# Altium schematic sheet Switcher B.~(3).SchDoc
size 431 x 279 mm; Organization: UTVATE; Address1: ADDRESS 1; Address2: ADDRESS 2; Address3: ADDRESS 3; Address4: ADDRESS 4; Revision: -; SheetNumber: 1; SheetTotal: 1; ENG_APP_DATE: YYYY/MM/DD; DSN_APP_DATE: YYYY/MM/DD; CHK_APP_DATE: YYYY/MM/DD
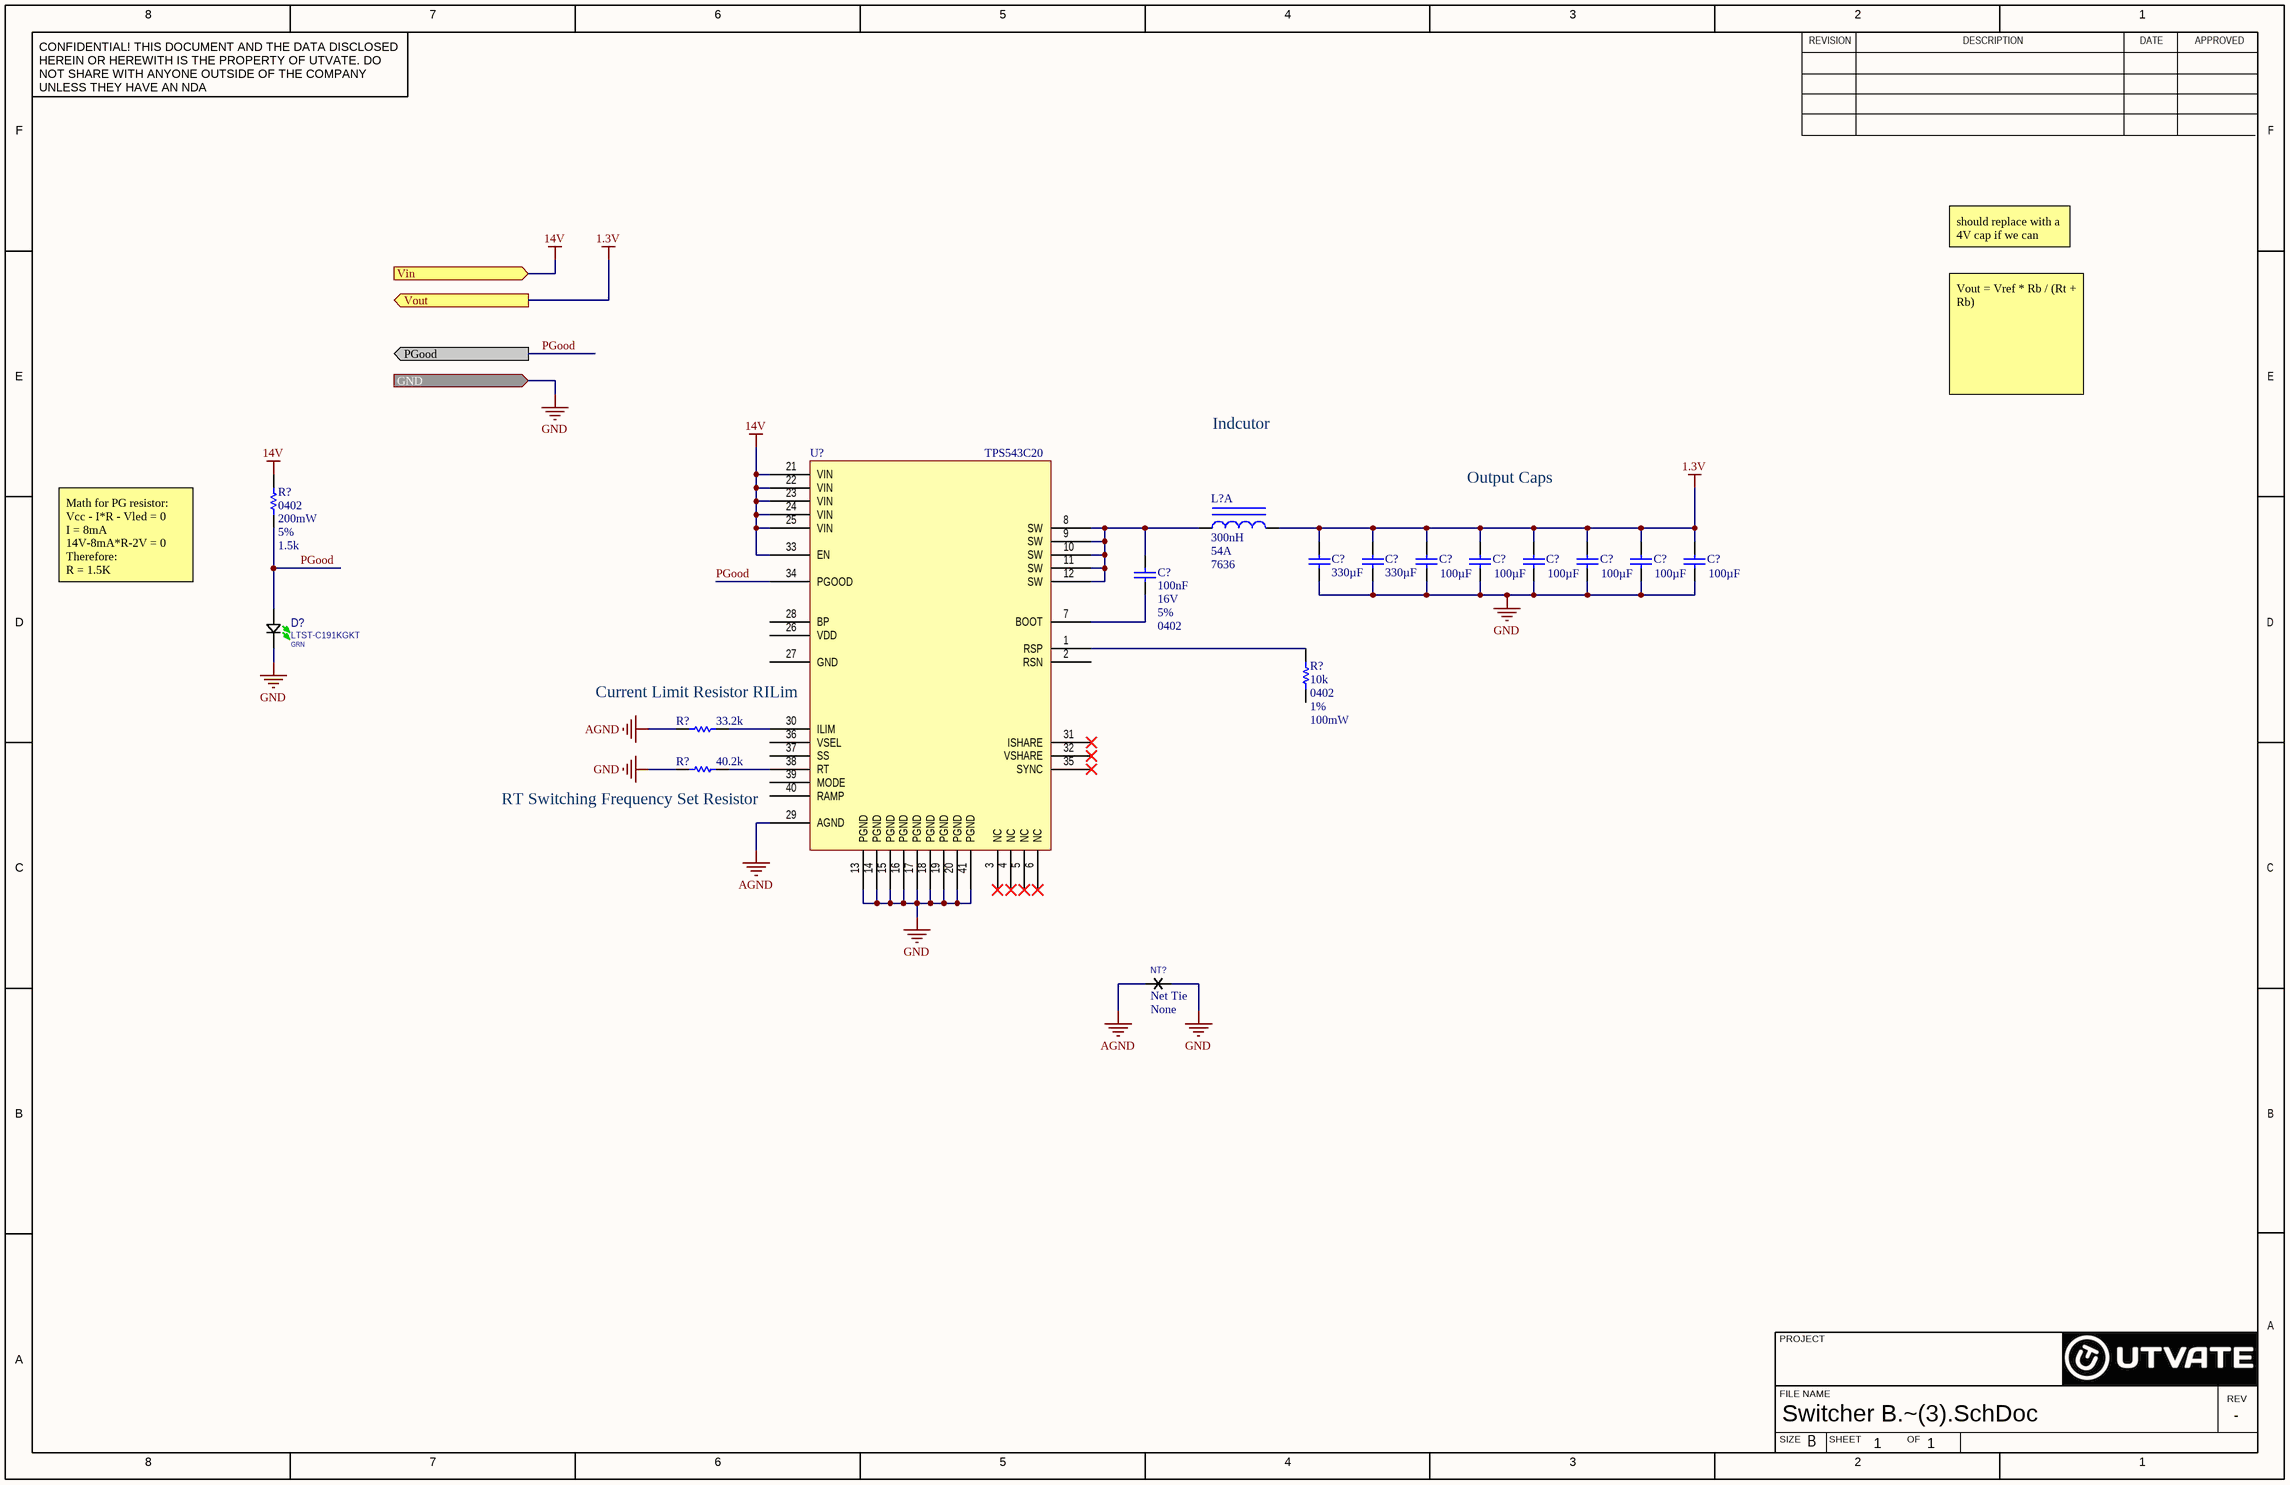
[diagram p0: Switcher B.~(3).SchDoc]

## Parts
(Parts that share a designator on the sheet are numbered #1, #2 ... from top to bottom, then left to right.)
C?#1  value 330µF  [CAP_1210_Most]  (hidden comment: GRM32ER60G337ME05L)
C?#2  value 330µF  [CAP_1210_Most]  (hidden comment: GRM32ER60G337ME05L)
C?#3  value 100µF  [CAP_0805_Nominal]  (hidden comment: GRM21BR60J107ME15K)
C?#4  value 100µF  [CAP_0805_Nominal]  (hidden comment: GRM21BR60J107ME15K)
C?#5  value 100µF  [CAP_0805_Nominal]  (hidden comment: GRM21BR60J107ME15K)
C?#6  value 100µF  [CAP_0805_Nominal]  (hidden comment: GRM21BR60J107ME15K)
C?#7  value 100µF  [CAP_0805_Nominal]  (hidden comment: GRM21BR60J107ME15K)
C?#8  value 100µF  [CAP_0805_Nominal]  (hidden comment: GRM21BR60J107ME15K)
C?#9  value 100nF  Voltage Rating: 16V  Tolerance: 5%  Case/Package: 0402  [CAP_0402_Nominal]  (hidden comment: GRM155R71C104JA88D)
D?  LTST-C191KGKT  Color: GRN  [DIOC1608X06N]
L?  value 300nH  Max Current: 54A  Case/Package: 7636  [COIL-SER2009-3_V]  (hidden comment: 300nH Inductor)  (part A of 2)
NT?  Net Tie  Manufacturer: None  [Net Tie-Footprint-1]  (net tie, no BOM)
R?#1  value 1.5k  Case/Package: 0402  Power: 200mW  Tolerance: 5%  [RESC1005X40X25ML05T10]  (hidden comment: RCS04021K50JNED)
R?#2  value 10k  Case/Package: 0402  Tolerance: 1%  Power: 100mW  [RES_0402_Most]  (hidden comment: ERJ-2RKF1002X)
R?#3  value 33.2k  [RES_0402_Most]  (hidden comment: CRCW040233K2FKED)
R?#4  value 40.2k  [RES_0402_Nominal]  (hidden comment: Res 40.2K 0402)
U?  TPS543C20  [TPS543C20 -Footprint-1]

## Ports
GND (in), PGood (out), Vin (in), Vout (out)

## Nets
1.3V: C?#1.2 C?#2.2 C?#3.2 C?#4.2 C?#5.2 C?#6.2 C?#7.2 C?#8.2 L?.2 ; port Vout
14V: R?#1.2 U?.21(VIN) U?.22(VIN) U?.23(VIN) U?.24(VIN) U?.25(VIN) U?.33(EN) ; port Vin
AGND: NT?.1 R?#3.1 U?.29(AGND)
GND: C?#1.1 C?#2.1 C?#3.1 C?#4.1 C?#5.1 C?#6.1 C?#7.1 C?#8.1 D?.1 NT?.2 R?#4.1 U?.13(PGND) U?.14(PGND) U?.15(PGND) U?.16(PGND) U?.17(PGND) U?.18(PGND) U?.19(PGND) U?.20(PGND) U?.41(PGND) ; port GND
PGood: D?.2 R?#1.1 U?.34(PGOOD) ; port PGood
NetC?#9_1: C?#9.1 U?.7(BOOT)
NetC?#9_2: C?#9.2 L?.1 U?.8(SW) U?.9(SW) U?.10(SW) U?.11(SW) U?.12(SW)
NetR?#2_1: R?#2.1 U?.1(RSP)
NetR?#3_2: R?#3.2 U?.30(ILIM)
NetR?#4_2: R?#4.2 U?.38(RT)

Not connected (* = marked no-connect by the designer): R?#2 2; U? 2(RSN) 3(NC)* 4(NC)* 5(NC)* 6(NC)* 26(VDD) 27(GND) 28(BP) 31(ISHARE)* 32(VSHARE)* 35(SYNC)* 36(VSEL) 37(SS) 39(MODE) 40(RAMP)

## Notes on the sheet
- should replace with a 4V cap if we can
- Indcutor
- Vout = Vref * Rb / (Rt + Rb)
- Output Caps
- Math for PG resistor:
  Vcc - I*R - Vled = 0
  I = 8mA
  14V-8mA*R-2V = 0
  Therefore:
  R = 1.5K
- Output Capacitance:
  ~
  300uF output capacitance which reduces output ripple but avoids introducing loop instability.
  2x330uF caps utilized to decrease footprint.
- (near U?) Current Limit Resistor RILim
- (near C?#4) Inductor Selection:
  Datasheet: https://www.coilcraft.com/getmedia/56db8f04-6d7a-4e93-ad3f-acf7c2a14b74/ser2000.pdf
  IMax and ISat chosen > 2x 25.5A(max operating current)
  SFR Chosen > decade higher switching frequency(500KHz)
  300nH to meet goal 320nH from TI TPS543C20 Design Calculator E equation.( Gives optimized choice for meeting operating needs and switching current ripple at 500KHz)
- RILim chosen to set current limit at 35A. This can be reduced once we have verified 25.5A max operating current.
- RT Switching Frequency Set Resistor
- (near U?) Rt chosen to set switching frequency at 500KHz
  500KHz is TI's recommended switching frequency for TPS543C20 for applications trying to achieve the parts maximum efficiency.

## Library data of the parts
C?#1 C?#2 = CMP-001-00015-15: Cap 330uF 1210 4V; Manufacturer: Murata; Capacitor Type: Ceramic; Tolerance: 20%; Dielectric: X5R
C?#3-C?#8 = CMP-001-00022-9: Cap 100uF 0805 6.3V; Manufacturer: Murata; Tolerance: 20%; Dielectric: X5R; Capacitor Type: Ceramic
C?#9 = CMP-001-00001-23: Cap 100nF 0402 16V; Manufacturer: Murata; Capacitor Type: Ceramic; Dielectric: X7R
D? = CMP-011-0002-3: LED, GREEN, 0603, 2V; Manufacturer: Lite-On Inc.; Forward Current: 20mA
L? = CMP-006-00014-1: General Purpose Inductor, 0.3uH, 20%, 1 Element, Ferrite-Core, SMD, 7636; Manufacturer Part Number: SER2009-301MLD; Manufacturer: CoilCraft; Case/Size Code: 7674; Inductor Application: POWER INDUCTOR; Package Width: 18.7mm; Max Current Rating: 100A; Package Length: 19.18mm; Shielding: Unshielded; Shape/Size Description: RECTANGULAR PACKAGE; Self Resonant Frequency: 550MHz; Package Height: 8.64mm; Channels: 1; Test Frequency: 100kHz; DC Resistance (DCR): 0.74mR
NT? = CMP-006-0011-2: All Copper net tie to join two nets together in a specific location
R?#1 = CMP-009-00072-1: Res 1.5K 0402; Manufacturer: Vishay Dale
R?#2 = CMP-009-00012-12: Res 10k 0402; Manufacturer: Panasonic; Temperature Coefficient: 100ppm/°C; Voltage Rating: 50V
R?#3 = CMP-009-00011-12: Res 33.2k 0402; Manufacturer: Vishay Dale; Temperature Coefficient: 100ppm/°C; Power: 63mW; Tolerance: 1%; Voltage Rating: 50V
R?#4 = CMP-009-00082-1: 40.2K 0402; Manufacturer Part Number: RCS040240K2FKED; Manufacturer: Vishay Dale; Power: 200mW; Tolerance: 1%
U? = CMP-019-00006-1: Switching Regulator, Current-mode, 40A, 2000kHz Switching Freq-Max, PQCC40; Manufacturer: Texas Instruments; Min Supply Voltage: 4V; Output Voltage: 5.5V; Max Supply Voltage: 16V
